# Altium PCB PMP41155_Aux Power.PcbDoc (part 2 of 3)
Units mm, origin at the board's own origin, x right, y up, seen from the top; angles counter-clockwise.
Board outline 40.5 x 70.5 mm, 6 copper layers (Top Layer, Signal Layer 1, Signal Layer 2, Signal Layer 3, Signal Layer 4, Bottom Layer), stack 1.573 mm thick; 130 components, 63 nets, 392 pads, 295 vias.
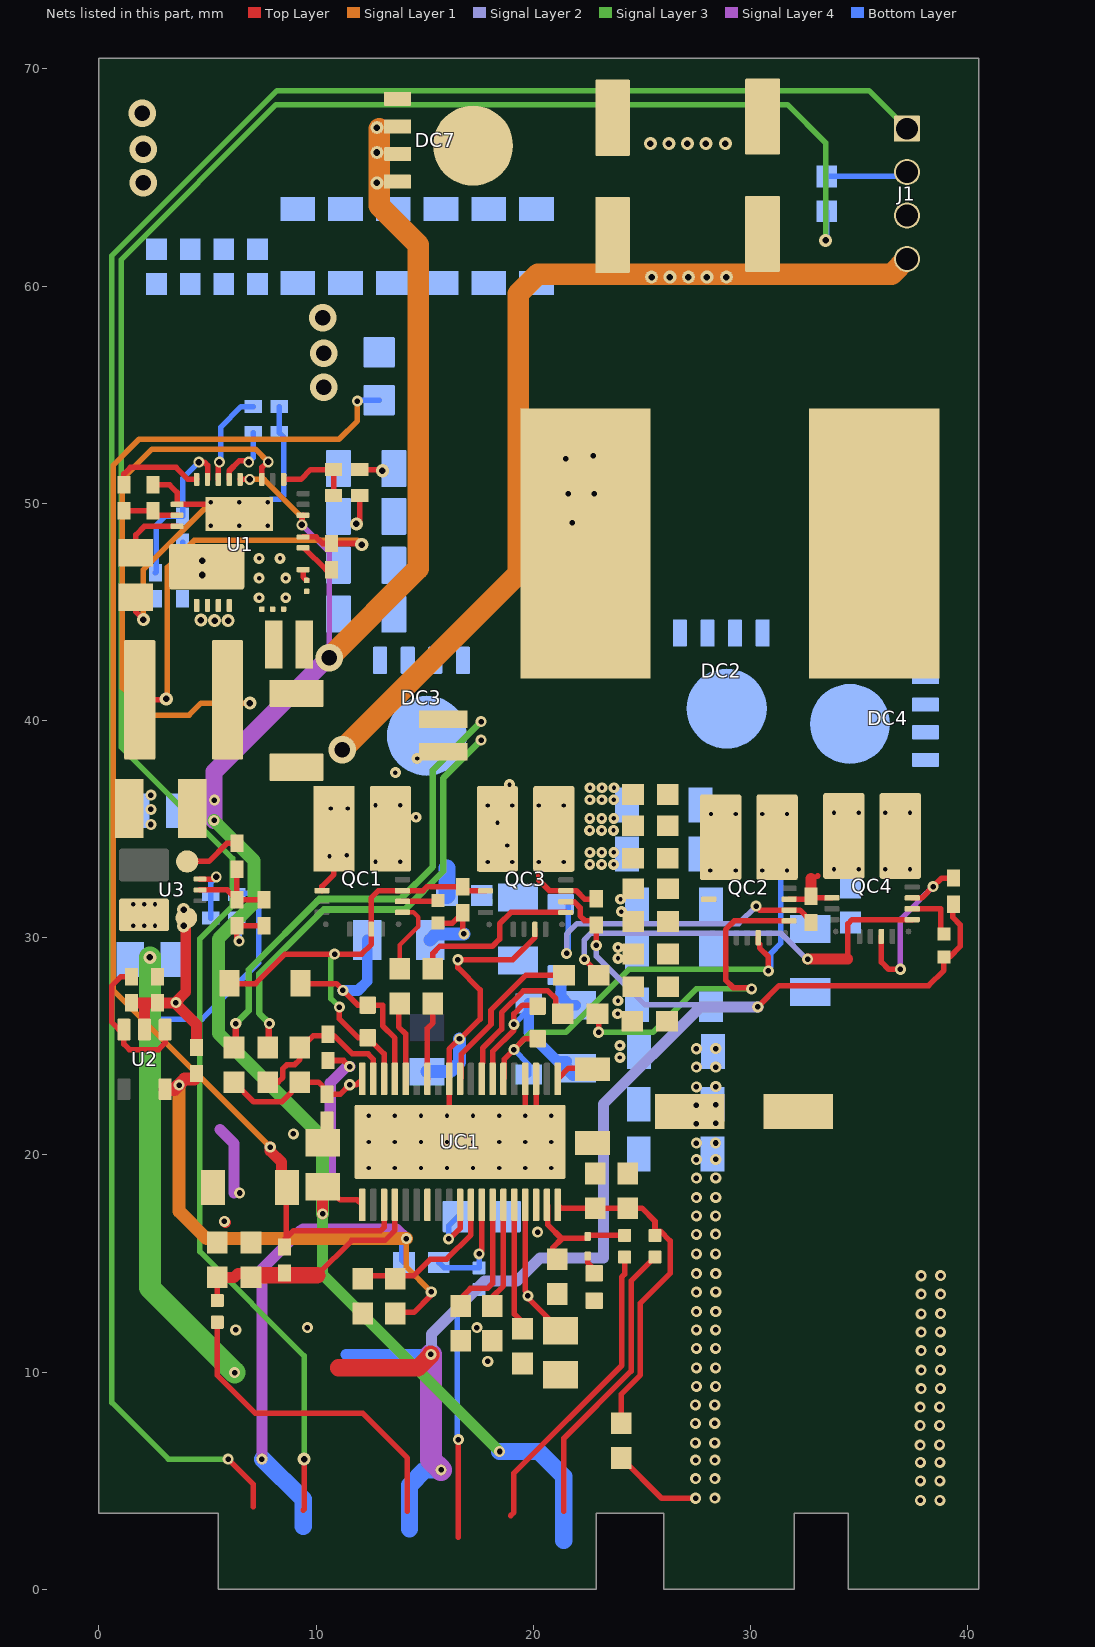
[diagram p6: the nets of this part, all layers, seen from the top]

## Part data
C1 C2: library part CMP-0007473-4, "CAP, CERM, 1800 pF, 100 V, +/- 10%, X7R, 0603", Cap_Case=0603, Manufacturer=MuRata, Supplier Part Number 1=490-1477-1-ND, TempCo=X7R, Tolerance_%=10%, Value1=Unknown, Value2=100V, ValueDisplayed=1800pF
C3 C12: library part CMP-0080610-1, "CAP, CERM, 0.1 µF, 25 V,+/- 10%, X7R, AEC-Q200 Grade 1, 0402", Cap_Case=0402, Manufacturer=TDK, Supplier Part Number 1=445-6902-1-ND, TempCo=X7R, Tolerance_%=10%, Value2=25V, ValueDisplayed=0.1µF
C4 C5 C6 C7: library part CMP-0125197-1, "100V 4.7uF X7R ±20% 1206 Multilayer Ceramic Capacitors MLCC - SMD/SMT ROHS", Manufacturer=HRE, Operating Temperature Range="-55°C to +125°C", TempCo=15%, Temperature Characteristic=X7R, Tolerance_%=20%, ValueDisplayed=4.7uF
C8: library part CMP-0080701-1, "CAP, CERM, 4.7 µF, 16 V,+/- 10%, X7R, AEC-Q200 Grade 1, 0805", Cap_Case=0805, Manufacturer=TDK, Supplier Part Number 1=445-8788-1-ND, TempCo=X7R, Tolerance_%=10%, Value2=16V, ValueDisplayed=4.7µF
C9: library part CMP-0091700-1, "47µF ±10% 16V Ceramic Capacitor X5R 1210 (3225 Metric)", Digikey Part Number=587-EMK325ABJ476KMHPCT-ND, Manufacturer="Taiyo Yuden", Mouser Part Number=963-EMK325ABJ476KMHP, Operating Temperature Range="-55°C to +85°C", TempCo=15%, Temperature Characteristic=X5R, Tolerance_%=10%, ValueDisplayed=47uF
C10: library part CMP-0006312-2, "CAP, CERM, 47 pF, 50 V, +/- 5%, C0G/NP0, AEC-Q200 Grade 0, 0402", Cap_Case=0402, Manufacturer=TDK, Supplier Part Number 1=445-12142-1-ND, TempCo=C0G/NP0, Tolerance_%=5%, Value1=Unknown, Value2=50V, ValueDisplayed=47pF
C11: library part CMP-0006323-2, "CAP, CERM, 6800 pF, 50 V, +/- 10%, X7R, AEC-Q200 Grade 1, 0402", Cap_Case=0402, Manufacturer=TDK, Supplier Part Number 1=445-6892-1-ND, TempCo=X7R, Tolerance_%=10%, Value1="0.391597 ohm", Value2=50V, ValueDisplayed=6800pF
C13 C14 C22: library part CMP-0006371-2, "CAP, CERM, 0.1 uF, 6.3 V, +/- 10%, B, 0402", Cap_Case=0402, Manufacturer=MuRata, Supplier Part Number 1=GRM155R70J104KA01D-ND, TempCo=B, Tolerance_%=10%, Value1=Unknown, Value2=6.3V, ValueDisplayed=0.1uF
C15 C16: library part CMP-0124190-1, "270 µF 16 V Aluminum - Polymer Capacitors Radial, Can - SMD 10mOhm 15000 Hrs @ 105°C", Digikey Part Number=565-APXJ160ARA271MF80JCT-ND, Leakage Current=864uA, Manufacturer=Chemi-Con, Mouser Part Number=661-XJ160ARA271MF80J, Operating Temperature Range="-55°C to +105°C", Tolerance_%=20%, ValueDisplayed=270uF
C19: library part CMP-0009211-2, "CAP, CERM, 47 uF, 16 V, +/- 10%, X5R, 1210", Cap_Case=1210, Manufacturer=MuRata, Supplier Part Number 1=GRM32ER61C476KE15L-ND, TempCo=X5R, Tolerance_%=10%, Value1=Unknown, Value2=16V, ValueDisplayed=47uF
C20: library part CMP-0007728-2, "CAP, CERM, 1 uF, 25 V, +/- 10%, X7R, 0805", Cap_Case=0805, Manufacturer=Kemet, Supplier Part Number 1=399-8004-1-ND, TempCo=X7R, Tolerance_%=10%, Value1=Unknown, Value2=25V, ValueDisplayed=1uF
C21: library part CMP-0007989-2, "CAP, CERM, 22 uF, 6.3 V, +/- 10%, X5R, 0805", Cap_Case=0805, Manufacturer="Samsung Electro-Mechanics", TempCo=X5R, Tolerance_%=10%, Value1=Unknown, Value2=6.3V, ValueDisplayed=22uF
C23: library part CMP-0078218-1, "CAP, CERM, 0.01 µF, 16 V,+/- 10%, X7R, 0402", Cap_Case=0402, Manufacturer=Kemet, Supplier Part Number 1=399-1038-1-ND, TempCo=X7R, Tolerance_%=10%, Value2=16V, ValueDisplayed=0.01µF
CC1 CC2 CC3 CC4 CC5 CC6 CC19 CC20 CC21 CC22 CC23 CC27 CC28 CC29 CC34 CC37: library part C3216X6S1H475K160AB, "CAP CER 4.7UF 100V X7S 1206", Cap_Case=1206, TempCo=X7S, Tolerance_%=10, Value2=100V, ValueDisplayed=4.7µF
CC7 CC8 CC9 CC10 CC11 CC12 CC13 CC14 CC15 CC16 CC17 CC18: "CAP, CERM, 0.022 µF, 100 V,+/- 10%, X7R, AEC-Q200 Grade 1, 0603", Cap_Case=0603, Manufacturer=TDK, Supplier Part Number 1=445-5814-1-ND, TempCo=X7R, Tolerance_%=10, Value1="0.083542 ohm", Value2=100V, ValueDisplayed=0.022µF
CC24 CC25 CC30 CC31: "CAP, CERM, 0.1 µF, 16 V,+/- 10%, X7R, AEC-Q200 Grade 1, 0402", Cap_Case=0402, Manufacturer=Kemet, Supplier Part Number 1=399-6828-1-ND, TempCo=X7R, Tolerance_%=10, Value2=16V, ValueDisplayed=0.1µF
CC26: library part EEE-FK1H220P, "CAP ALUM POLY HYB 22UF 63V SMD", Cap_Case=D, Manufacturer=Rubycon, Tolerance_%=20, Value1="0.88 ohm", Value2=63V, ValueDisplayed=22µF
CC32: library part CMP-0078699-1, "CAP, CERM, 47 µF, 10 V,+/- 20%, X5R, 0805", Cap_Case=0805, Manufacturer=MuRata, Supplier Part Number 1=490-9961-1-ND, TempCo=X5R, Tolerance_%=20%, Value2=10V, ValueDisplayed=47µF
CC33: "CAP, CERM, 220 pF, 50 V,+/- 10%, X7R, 0603", Cap_Case=0603, Manufacturer=MuRata, Supplier Part Number 1=490-1483-1-ND, TempCo=X7R, Tolerance_%=10, Value2=50V, ValueDisplayed=220pF
CC35: "CAP, CERM, 2.2 µF, 25 V,+/- 10%, X5R, 0805", Cap_Case=0805, Manufacturer=MuRata, Supplier Part Number 1=490-1701-1-ND, TempCo=X5R, Tolerance_%=10, Value1="0.006 ohm", Value2=25V, ValueDisplayed=2.2µF
CC36: "CAP, CERM, 68 pF, 50 V,+/- 5%, C0G/NP0, 0603", Cap_Case=0603, Manufacturer=AVX, Supplier Part Number 1=478-1173-1-ND, TempCo=C0G/NP0, Tolerance_%=5, Value1="0.144 ohm", Value2=50V, ValueDisplayed=68pF
CC38: "CAP, CERM, 1000 pF, 50 V,+/- 5%, C0G/NP0, 0603", Cap_Case=0603, Manufacturer=MuRata, Supplier Part Number 1=490-1451-1-ND, TempCo=C0G/NP0, Tolerance_%=5, Value2=50V, ValueDisplayed=1000pF
CC39 CC40: "CAP, CERM, 47 pF, 50 V,+/- 1%, C0G/NP0, 0402", Cap_Case=0402, Manufacturer=MuRata, Supplier Part Number 1=490-6241-1-ND, TempCo=C0G/NP0, Tolerance_%=1, Value2=50V, ValueDisplayed=47pF
CC41: "CAP, CERM, 2200 pF, 50 V,+/- 10%, X5R, 0603", Cap_Case=0603, Manufacturer=MuRata, Supplier Part Number 1=GRM188R61H222KA01D-ND, TempCo=X5R, Tolerance_%=10, Value2=50V, ValueDisplayed=2200pF
CC42 CC43: library part CMP-0120699-1, "0.1 µF ±5% 16V Ceramic Capacitor X7R 0603 (1608 Metric)", Digikey Part Number=478-KGM15AR71C104JTCT-ND, Manufacturer="KYOCERA AVX", Mouser Part Number=581-0603YC104J, Operating Temperature Range="-55°C to +125°C", TempCo=15%, Temperature Characteristic=X7R, Tolerance_%=5%, ValueDisplayed=100nF
CC44: library part CMP-0095696-1, "Cap Ceramic 22nF 50V X7R ±10% Pad SMD 0603 +125°C T/R", Manufacturer=Samsung, Operating Temperature Range="-55°C to +125°C", TempCo=0.15, Temperature Characteristic=X7R, Tolerance_%=10%, ValueDisplayed=22nF
CC45: library part CMP-0007168-4, "CAP, CERM, 820 pF, 25 V, +/- 5%, C0G/NP0, 0603", Cap_Case=0603, Manufacturer=MuRata, Supplier Part Number 1=81-GRM185C1E821JA01D, TempCo=C0G/NP0, Tolerance_%=5%, Value1=Unknown, Value2=25V, ValueDisplayed=820pF
CC46: library part CMP-0007572-2, "CAP, CERM, 0.22 uF, 25 V, +/- 20%, X7R, 0805", Cap_Case=0805, Manufacturer=AVX, Supplier Part Number 1=478-3757-1-ND, TempCo=X7R, Tolerance_%=20%, Value1="0.016 ohm", Value2=25V, ValueDisplayed=0.22uF
DC1: library part CMP-0090564-1, "Diode Schottky 40V 500mA Surface Mount SOD-123", Digikey Part Number=NRVB0540T1GOSCT-ND, Forward Current=0.5A, Manufacturer="On Semiconductor", Max Surge Forward Current=5.5A, Mouser Part Number=863-NRVB0540T1G, Operating Temperature Range="-55°C to +150°C", Peak Reverse Current=20uA
DC2 DC3 DC4 DC7: library part CMP-0032275-1, "Diode 100 V 30A Surface Mount PowerFlat™ (5x6)", Digikey Part Number=497-10342-1-ND, Forward Current=30A, Manufacturer=STMicroelectronics, Max Surge Forward Current=200A, Mouser Part Number=511-STPS30M100DJF-TR, Operating Temperature Range="to +150°C", Peak Reverse Current=100uA
DC5 DC6: library part CMP-0077600-3, "Diode, Zener, 5.6 V, 500 mW, SOD-123", Manufacturer=Vishay-Semiconductor, Power_W=500mW, Value1=0.5W
J1: library part CMP-0125223-1, "Conn Socket Strip SKT 4 POS 2mm Solder ST Thru-Hole Box", Current_A=3A, Digikey Part Number=831-87-004-10-001101-ND, Manufacturer=Preci-Dip, Mouser Part Number=437-8318700410001101, Operating Temperature Range="-55°C to +125°C", Voltage_V=150V
L1: library part CMP-0093175-1, "Shielded Power Inductors 3.3uH 20% tol, 6.5mOhm 16.6A", Manufacturer=Coilcraft, Operating Temperature Range=to, Self Resonant Frequency=24MHz, Test Frequency=1MHz, Tolerance_%=20%
LC1: library part CMP-0064042-1, ValueDisplayed=2.2uH
LOGO1: library part CMP-0074837-1, "IEC 61010-1 Hot Surface Warning"
Logo2: library part Pb-Free
Logo3: library part CMP-0074769-1
Logo4: library part CMP-0074847-1, "FCC_disclaimer"
QC1 QC2 QC3 QC4: library part CMP-0037654-1, "100-V, 64-A GaN with Integrated Driver", Manufacturer="Texas Instruments", Max Supply Voltage=5.25V, Min Supply Voltage=4.75V, Nominal Supply Current=3mA, Operating Temperature Range="-40°C to +125°C"
R1 R2: library part CMP-02407-004899-1, "RES Thick Film, 3.01Ω, 1%, 0.063W, 200ppm/°C, 0402", Case Code (Imperial)=0402, Case Code (Metric)=1005, Max Operating Temperature=155°C, Max Power Dissipation=63mW, Min Operating Temperature=-55°C, Package Quantity=10000, Resistance=3.01R, Temperature Coefficient=200ppm/°C, Tolerance=1%, Voltage Rating=50V
R3 R4: library part CMP-0016888-3, "RES, 2.55, 1%, 0.25 W, AEC-Q200 Grade 0, 1206", Manufacturer=Vishay-Dale, Power_W=250mW, Supplier Part Number 1=541-2.55FFCT-ND, TempCo="100 ppm/C", Tolerance_%=1%, Value2=0.25W, Value_Code=2R55, ValueDisplayed=2.55
R5: library part CMP-0022550-4, "RES, 681 k, 1%, 0.1 W, AEC-Q200 Grade 0, 0603", Manufacturer=Vishay-Dale, Power_W=100mW, Supplier Part Number 1=541-681KHCT-ND, TempCo="100 ppm/C", Tolerance_%=1%, Value2=0.1W, Value_Code=681k
R6 R8 R9 R10: library part CMP-0031873-1, "0 Ohms Jumper Chip Resistor 0402 (1005 Metric) Anti-Sulfur, Current Sense, Flame Retardant Coating, Moisture Resistant, Safety Metal Foil", Digikey Part Number=4463-D1LPC0402CJUMPF-T10CT-ND, Manufacturer="Thin Film Technology", Max Current=20A, Operating Temperature Range="-55°C to +170°C"
R7: library part CMP-0022042-4, "RES, 13.0 k, 1%, 0.1 W, AEC-Q200 Grade 0, 0603", Manufacturer=Vishay-Dale, Power_W=100mW, Supplier Part Number 1=541-13.0KHCT-ND, TempCo="100 ppm/C", Tolerance_%=1%, Value2=0.1W, Value_Code=13k0, ValueDisplayed=13.0k
R11: library part CMP-0026753-1, "RES, 100 k, 1%, 0.063 W, AEC-Q200 Grade 0, 0402", Manufacturer="Stackpole Electronics Inc", Power_W=63mW, Supplier Part Number 1=RMCF0402FT100KCT-ND, TempCo="100 ppm/C", Tolerance_%=1%, Value2=0.063W, Value_Code=100k
R12: library part CMP-0015100-2, "RES, 0.005, 1%, 1 W, AEC-Q200 Grade 0, 0508", Manufacturer="Susumu Co Ltd", Power_W=1W, Supplier Part Number 1=754-KRL2012MR005FT1, TempCo="25 ppm/C", Tolerance_%=1%, Value_Code=5L000, ValueDisplayed=0.005
R13: library part CMP-0026468-2, "RES, 5.76 k, 1%, 0.063 W, AEC-Q200 Grade 0, 0402", Manufacturer=Vishay-Dale, Power_W=63mW, Supplier Part Number 1=541-5.76KLCT-ND, TempCo="100 ppm/C", Tolerance_%=1%, Value2=0.063W, Value_Code=5k76, ValueDisplayed=5.76k
R14: library part CMP-0026718-1, "RES, 49.9 k, 1%, 0.063 W, 0402", Manufacturer=Rohm, Power_W=63mW, Supplier Part Number 1=RHM49.9KLCT-ND, TempCo="100 ppm/C", Tolerance_%=1%, Value2=0.063W, Value_Code=49k9, ValueDisplayed=49.9k
R15: library part CMP-0026535-2, "RES, 71.5 k, 1%, 0.063 W, AEC-Q200 Grade 0, 0402", Manufacturer=Vishay-Dale, Power_W=63mW, Supplier Part Number 1=541-71.5KLCT-ND, TempCo="100 ppm/C", Tolerance_%=1%, Value2=0.063W, Value_Code=71k5, ValueDisplayed=71.5k
R16: library part CMP-0026163-2, "RES, 20.5 k, 1%, 0.063 W, AEC-Q200 Grade 0, 0402", Manufacturer=Vishay-Dale, Power_W=63mW, Supplier Part Number 1=541-20.5KLCT-ND, TempCo="100 ppm/C", Tolerance_%=1%, Value2=0.063W, Value_Code=20k5, ValueDisplayed=20.5k
R17 R19: library part CMP-0026403-2, "RES, 49.9 k, 1%, 0.063 W, AEC-Q200 Grade 0, 0402", Manufacturer=Vishay-Dale, Power_W=63mW, Supplier Part Number 1=541-49.9KLCT-ND, TempCo="100 ppm/C", Tolerance_%=1%, Value2=0.063W, Value_Code=49k9, ValueDisplayed=49.9k
R18: library part CMP-0025885-5, "RES, 0, 5%, 0.1 W, 0603", Manufacturer=Yageo, Power_W=100mW, Supplier Part Number 1=311-0.0GRCT-ND, TempCo="200 ppm/C", Tolerance_%=5%, Value2=0.1W, Value_Code=0000, ValueDisplayed=0
R20: library part CMP-0026728-1, "RES, 220 k, 1%, 0.0625 W, 0402", Manufacturer="Yageo America", Power_W=62.5mW, Supplier Part Number 1=311-220KLRCT-ND, TempCo="100 ppm/C", Tolerance_%=1%, Value2=0.0625W, Value_Code=220k
R21 R22: library part CMP-0078244-2, "RES, 30.0 k, 1%, 0.063 W, AEC-Q200 Grade 0, 0402", Manufacturer=Vishay-Dale, Power_W=63mW, Supplier Part Number 1=541-30.0KLCT-ND, TempCo="100 ppm/C", Tolerance_%=1%, Value2=0.063W, Value_Code=30k0, ValueDisplayed=30.0k
RC1 RC2: library part CMP-0018270-2, "RES, 3.30, 1%, 0.25 W, 1206", Manufacturer="Yageo America", Power_W=250mW, Supplier Part Number 1=311-3.30FRCT-ND, TempCo="200 ppm/C", Tolerance_%=1%, Value2=0.25W, Value_Code=3R30, ValueDisplayed=3.30
RC3: library part CMP-0015357-3, "RES, 0.002, 2%, 1 W, 0508", Manufacturer="Susumu Co Ltd", Power_W=1W, Supplier Part Number 1=408-1592-1-ND, TempCo="100 ppm/C", Tolerance_%=2%, Value_Code=2L000, ValueDisplayed=0.002
RC4 RC14: library part CMP-0096818-1, "0 Ohms Jumper 0.245W Chip Resistor 0805 (2012 Metric) - Metal Element", Digikey Part Number=JR0805X35ECT-ND, Manufacturer=Ohmite, Mouser Part Number=588-JR0805X35E, Operating Temperature Range="-55°C to +150°C", Power_W=245mW
RC5: library part CMP-0026535-2, "RES, 71.5 k, 1%, 0.063 W, AEC-Q200 Grade 0, 0402", Manufacturer=Vishay-Dale, Power_W=63mW, Supplier Part Number 1=541-71.5KLCT-ND, TempCo="100 ppm/C", Tolerance_%=1%, Value2=0.063W, Value_Code=71k5, ValueDisplayed=DNP
RC6 RC8: "RES, 100, 1%, 0.1 W, 0603", Manufacturer="Yageo America", Power_W=0.1, Supplier Part Number 1=311-100HRCT-ND, TempCo="200 ppm/C", Tolerance_%=1, Value1=1%, Value2=0.1W, Value_Code=100R, ValueDisplayed=100
RC7: "RES, 10.0 k, 1%, 0.1 W, 0603", Manufacturer=Vishay-Dale, Power_W=0.1, Supplier Part Number 1=541-10.0KHCT-ND, TempCo="100 ppm/C", Tolerance_%=1, Value1=1%, Value2=0.1W, Value_Code=10k0, ValueDisplayed=10.0k
RC9: "RES, 100, 1%, 0.1 W, 0603", Manufacturer=Vishay-Dale, Power_W=0.1, Supplier Part Number 1=541-100HCT-ND, TempCo="100 ppm/C", Tolerance_%=1, Value1=1%, Value2=0.1W, Value_Code=100R, ValueDisplayed=100
RC10: "RES, 10.7 k, 1%, 0.1 W, 0603", Manufacturer=Vishay-Dale, Power_W=0.1, Supplier Part Number 1=541-10.7KHCT-ND, TempCo="100 ppm/C", Tolerance_%=1, Value1=1%, Value2=0.1W, Value_Code=10k7, ValueDisplayed=10.7k
RC11 RC12 RC13 RC15: library part CMP-0025697-4, "RES, 0, 5%, 0.1 W, AEC-Q200 Grade 0, 0603", Manufacturer=Vishay-Dale, Power_W=100mW, Supplier Part Number 1=541-0.0GCT-ND, TempCo="200 ppm/C", Tolerance_%=5%, Value2=0.1W, Value_Code=0000, ValueDisplayed=0
RC16: library part CMP-0089989-1, "2.87 kOhms ±1% 0.1W, 1/10W Chip Resistor 0402 (1005 Metric) Automotive AEC-Q200, Moisture Resistant Thick Film", Digikey Part Number=2019-RK73H1ETTP2871FCT-ND, Manufacturer="KOA Speer", Mouser Part Number=660-RK73H1ETTP2871F, Operating Temperature Range="-55°C to +155°C", Power_W=100mW, TempCo=100ppm/°C, Tolerance_%=1%
RC17: "RES, 8.25 k, 1%, 0.1 W, 0603", Manufacturer=Vishay-Dale, Power_W=0.1, Supplier Part Number 1=541-8.25KHCT-ND, TempCo="100 ppm/C", Tolerance_%=1, Value1=1%, Value2=0.1W, Value_Code=8k25, ValueDisplayed=8.25k
RC18 RC19: "RES, 100 k, 1%, 0.1 W, 0603", Manufacturer=Vishay-Dale, Power_W=0.1, Supplier Part Number 1=541-100KHCT-ND, TempCo="100 ppm/C", Tolerance_%=1, Value1=1%, Value2=0.1W, Value_Code=100k
U1: library part CMP-0096026-3, "80-V, 8-A Synchronous DC/DC Buck Converter With Ultra-Low IQ, VQFN29", Manufacturer="Texas Instruments", Max Supply Voltage=80V, Min Supply Voltage=4.5V, Operating Temperature Range="-40°C to +150°C", Output Voltage=0.8-55V, Switching Frequency=0.2-2.2MHz
U2: library part CMP-0073750-1, "Capacitor-Free, 150-mA, LDO Regulator w/ Foldback Current Limit, DBV0005A (SOT-23-5)", Alternate Manufacturer="Texas Instruments"
U3: library part CMP-0097277-2, "3-V to 17-V Input, 3-A Synchronous Buck Module, QFN-FCMOD7", Manufacturer="Texas Instruments", Max Supply Voltage=17V, Min Supply Voltage=3V, Nominal Supply Current=100-400uA, Operating Temperature Range="-40°C to +125°C", Output Voltage=0.6-10V, Switching Frequency=1200/2000kHz
UC1: library part CMP-0094661-2, "Wide VIN Bidirectional 4 Switch Buck-Boost Controller", Manufacturer="Texas Instruments", Max Supply Voltage=78V, Min Supply Voltage=2.8V, Nominal Supply Current=25uA, Operating Temperature Range="-40°C to +125°C", Output Voltage=3.3-78V, Switching Frequency=100-2000kHz

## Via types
v1: diameter 0.508, hole 0.254, Top Layer to Bottom Layer, 138 vias
v2: diameter 0.5, hole 0.2, Top Layer to Bottom Layer, tented both sides, 64 vias
v3: diameter 0.5, hole 0.2, Top Layer to Bottom Layer, 48 vias
v4: diameter 0.6, hole 0.3, Top Layer to Bottom Layer, 29 vias
v5: diameter 1.27, hole 0.711, Top Layer to Bottom Layer, 8 vias
v6: diameter 0.5, hole 0.3, Top Layer to Bottom Layer, 7 vias
v7: diameter 0.508, hole 0.254, Top Layer to Bottom Layer, tented both sides, 1 vias

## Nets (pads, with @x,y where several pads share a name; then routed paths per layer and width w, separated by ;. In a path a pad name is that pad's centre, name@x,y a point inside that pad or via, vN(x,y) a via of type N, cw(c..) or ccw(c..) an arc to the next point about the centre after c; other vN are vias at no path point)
3V3: C13.1 RC7.1 RC9.1 U2.5 | length 45.1
  Top Layer w0.254: RC9.1@13.5,12.75 14.5,12.75 15.3,13.55 v1@15.3,13.75
  Top Layer w0.6: U2.5@3.05,23.025 3.475,23.025 3.95,23.5 C13.1@4.4,23.5
  Signal Layer 4 w0.508: v1(7.5,6) 7.5,14.75 9.271,16.521 9.302,16.521 9.385,16.603 13.697,16.603 v1(14.15,16.15)
  Signal Layer 1 w0.254: v1(14.15,16.15) 14.15,14.85 v1(15.3,13.7)
  Signal Layer 1 w0.6: v1(3.695,23.214) 3.695,17.405 4.95,16.15 v1(14.15,16.15)
  Bottom Layer w0.254: v1(7.5,6) v1@7.55,6 ; RC7.1@14.05,15.05 13.95,15.15 13.95,15.85 v1@14.2,16.1
  Bottom Layer w0.8: v1@7.55,6 9.4,4.15 9.4,2.9
5V: C14.1 C21.1 C22.1 CC30.1 CC31.1 QC3.3 R2.2 R20.2 U2.1 U2.3 U3.3 | length 106.4
  Top Layer w0.254: C22.1@1.5,28.2 1,28.2 0.6,27.8 0.6,26.1 0.925,25.775 U2.3@1.15,25.775 1.15,25.1 1.4,24.85 2.75,24.85 3.05,25.15 U2.1@3.05,25.775 ; QC3.3@21.495,31.663 21.716,31.663 21.718,31.661 21.873,31.661 21.942,31.593 22.154,31.381 22.154,31.004 22.367,30.791 22.722,30.791 22.895,30.618 CC30.1@22.895,30.588 v1(22.895,29.653) ; v1(30.33,26.814) 31.315,27.8 38.2,27.8 38.9,28.5 R2.2@38.9,29.125 39.175,29.125 39.65,29.6 39.65,30.6 39.3,30.95 39.3,31.5 CC31.1@39.35,31.55
  Top Layer w0.8: 11.031,10.2 14.7,10.2 15.284,10.784 v1(15.284,10.819)
  Signal Layer 4 w1: v1(15.284,10.819) 15.284,5.966 v1(15.75,5.5)
  Signal Layer 3 w1: v4(2.35,29.1) 2.35,13.885 v1(6.25,9.985)
  Signal Layer 2 w0.254: v1(22.895,29.653) 22.895,29.155 25.136,26.914 27.914,26.914
  Signal Layer 2 w0.508: v1@15.306,10.819 15.306,11.756 17.753,14.203 19.253,14.203 20.3,15.25 23.229,15.25 23.229,22.358 27.686,26.814 v1(30.33,26.814)
  Bottom Layer w0.254: 2.4,28.6 2.4,26.6 2.75,26.25 4.75,26.25 7.35,28.85 7.35,31.85 7.15,32.05 6.4,32.05 R20.2@6.35,32
  Bottom Layer w0.508: 11.369,10.819 v1(15.284,10.819)
  Bottom Layer w0.8: 14.3,2.8 14.3,4.8 15,5.5 v1(15.75,5.5)
  other v3: 1.585,30.55 2.085,30.55 2.585,30.55 1.585,31.55 2.085,31.55 2.585,31.55
12V: C9.2 C19.1 C20.1 CC35.2 DC7.1 DC7.2 DC7.3 DC7.4 R12.2 R19.2 U1.6 U1.12 U3.1 UC1.1 | length 96.4
  Top Layer w0.254: U3.1@4.062,33.512 5.062,33.512 5.9,34.35 R19.2@6.35,34.35 ; U1.12@6.5,51.1 v6(6.941,51.1) ; v6(9.345,49.006) 9.345,49.395 U1.6@9.4,49.45 ; CC35.2@10.434,18.158 10.878,18.158 11.1,17.936 11.889,17.936 UC1.1@12.125,17.7
  Top Layer w0.508: v1(10.3,17.289) 10.3,18.267 CC35.2@10.434,18.4
  Signal Layer 4 w0.254: v6(9.345,49.006) 10.6,47.751 v5(10.6,42.9)
  Signal Layer 4 w0.8: v1(5.3,35.4) 5.3,37.65 v5@10.55,42.9
  Signal Layer 3 w0.508: v1(10.3,17.289) 10.3,14.5 v1(18.45,6.35)
  Signal Layer 3 w0.6: v1(5.3,35.4) 7.15,33.55 7.15,31.6 5.5,29.95 5.5,25.6 10.3,20.8 v1(10.3,17.289)
  Signal Layer 1 w0.254: v6(6.941,51.1) 7.6,51.1 9.35,49.35 v6@9.35,49.05
  Signal Layer 1 w1: v5(10.6,42.9) 14.7,47 14.7,61.9 12.9,63.7 ; v4@12.9,64.75 12.9,63.7 ; v4@12.9,67.25 12.9,66.15 12.9,63.7
  Bottom Layer w0.8: v1(18.45,6.35) 20.25,6.35 21.4,5.2 21.4,2.25
  other v1: 5.311,36.338
  other v4: 12.8,64.75 12.8,66.15 12.8,67.3
12VFAN: C15.2 C16.2 DC7.5 J1.3
  other v4: 25.389,66.563 26.239,66.563 27.089,66.563 27.939,66.563 28.839,66.563
CSA_DISCH: C2.1 CC24.2 CC42.2 DC3.5 DC5.2 QC1.4 QC1.6 QC1.14 QC3.7 QC3.8 RC3.1 RC6.2 UC1.36 | length 43.8
  Top Layer w0.254: DC5.2@6.362,27.887 7.214,27.887 8.573,29.246 v1(10.846,29.246) 12.096,29.246 12.545,29.695 QC1.14@12.545,30.397 12.545,31.851 12.866,32.172 14.922,32.172 15.1,32.35 CC24.2@16.75,32.35 16.937,32.163 QC3.8@17.795,32.163 ; v1(11.071,26.806) 11.071,26.262 11.933,25.4 CC42.2@12.375,25.4 13.125,24.65 UC1.36@13.125,23.5
  Top Layer w0.305: RC6.2@7.82,25 7.82,26.02 v1(7.85,26.05)
  Signal Layer 3 w0.254: v1(10.846,29.246) 10.677,29.077 10.677,27.2 v1(11.071,26.806)
  Signal Layer 3 w0.305: v1(7.85,26.05) 7.383,26.517 7.383,28.331 10.351,31.3 14.087,31.3 15.848,33.061 15.848,37.348 v1@17.65,39.15
  Bottom Layer w0.254: 16.023,33.208 16.04,33.225
  Bottom Layer w0.8: C2.1@16.023,31.945 16.023,33.208
  other v1: 17.6,39.1
  other v2: 17.895,33.488 19.035,33.488 12.73,33.497 13.87,33.497 18.8,34.25 18.35,35.3 14.6,35.55 12.73,36.097 13.87,36.097 17.895,36.088 19.035,36.088 18.9,37.05 13.65,37.6 14.65,38.25
CSB_DISCH: LC1.1 RC3.2 RC8.2 | length 21.9
  Top Layer w0.305: RC8.2@6.22,24.95 6.3,25.03 v1(6.3,26.05)
  Signal Layer 3 w0.305: v1(6.3,26.05) 6.9,26.65 6.9,28.531 10.151,31.783 13.887,31.783 15.365,33.261 15.365,37.715 v1(17.6,39.95)
  other v1: 21.8,49.1 21.6,50.45 22.8,50.45 21.5,52.05 22.75,52.2
DISCH_COMP: CC45.1 R8.2 RC16.2 UC1.18 | length 5.7
  Top Layer w0.254: UC1.18@20.625,17.7 20.67,17.655 20.67,16.78 21.307,16.143 ; CC45.1@20.9,15.373 20.9,15.736 21.307,16.143 ; RC16.2@22.5,16.173 21.337,16.173 21.307,16.143 ; RC16.2@22.5,16.25 22.55,16.3 R8.2@24.2,16.3
DISCH_EN: CC38.1 R10.2 RC5.1 RC10.2 UC1.4 | length 11.5
  Top Layer w0.254: R10.2@5.45,13.3 RC10.2@5.45,14.367 ; 10.05,14.467 11.65,16.067 13.167,16.067 13.625,16.525 UC1.4@13.625,17.7
  Top Layer w0.508: RC10.2@5.45,14.367 6.217,14.367 6.4,14.55 6.817,14.55 CC38.1@7,14.367
  Top Layer w0.75: CC38.1@6.95,14.467 10.05,14.467
DISCH_SS: CC46.1 UC1.16 | length 6.4
  Top Layer w0.254: UC1.16@19.625,17.7 19.625,13.742 v1@19.75,13.617 ; v1(19.75,13.517) 19.75,13.416 CC46.1@21.25,11.916
  Signal Layer 3 w0.254: v1@19.695,13.562 v1@19.75,13.617
GHA: QC1.2 RC11.2 | length 3.6
  Top Layer w0.2: RC11.2@13.85,28.571 13.85,29.663 14.7,30.513 14.7,30.95 14.478,31.172 QC1.2@13.97,31.172
GHB: QC2.2 RC13.2 | length 15.5
  Top Layer w0.254: RC13.2@22.95,26.5 23,26.45 v1(23,25.65) ; v1(30.05,27.65) 30.001,27.699 29.201,27.699 28.85,28.05 28.85,30.377 29.248,30.775 QC2.2@31.775,30.775
  Signal Layer 3 w0.254: v1(23,25.65) 25.5,25.65 27.5,27.65 v1(30.05,27.65)
GLA: QC3.2 RC12.2 | length 8
  Top Layer w0.254: RC12.2@15.367,28.571 15.367,29.283 15.685,29.6 18.108,29.6 18.45,29.942 18.45,30.645 18.968,31.163 QC3.2@21.495,31.163
GLB: QC4.2 RC15.2 | length 19.3
  Top Layer w0.254: v1(22.35,29) 23.009,28.341 RC15.2@23.009,28.281 ; v1(32.625,29.019) v1@32.628,29.022 ; 34.475,29.022 34.475,30.636 34.676,30.837 QC4.2@37.443,30.837
  Top Layer w0.5: v1@32.628,29.022 34.475,29.022
  Signal Layer 2 w0.254: v1(22.35,29) 22.336,29.014 22.336,29.884 22.663,30.212 31.388,30.212 v1@32.628,28.972
HB1: CC42.1 DC5.1 RC1.1 UC1.35 | length 10.7
  Top Layer w0.254: DC5.1@9.638,27.887 10.928,27.887 v1(11.236,27.579) 11.915,26.9 CC42.1@12.375,26.9 13.056,26.9 13.056,25.949 13.625,25.38 UC1.35@13.625,23.5
  Bottom Layer w0.5: v1(11.236,27.579) 11.929,27.579 12.35,28 RC1.1@12.35,29.9
HB2: CC43.1 DC6.1 RC2.2 UC1.26 | length 10.3
  Top Layer w0.254: UC1.26@18.125,23.5 18.125,24.768 19.1,25.743 v1(19.1,26.016) 19.1,26.5 19.5,26.9 20.15,26.9 CC43.1@20.2,26.85
  Bottom Layer w0.254: v1(19.1,26.016) DC6.1@19.787,26.703
  Bottom Layer w0.5: DC6.1@19.787,26.979 19.787,26.703 19.787,25.645 21.116,24.316 RC2.2@21.532,24.316 ; RC2.2@21.48,24.008 21.825,23.664 21.825,23.767 RC2.2@21.532,24.06
NetC1_2: C1.2 R3.2
NetC2_2: C2.2 R4.2
NetC3_1: C3.1 L1.1 U1. U1.5 U1.20 U1.21 U1.22 | length 19.6
  Top Layer w0.254: L1.1@1.88,40.95 3.05,40.95 v4(3.1,41) ; U1.5@9.4,48.45 10,48.45 10.3,48.15 12.05,48.15 v4(12.1,48.1)
  Signal Layer 1 w0.254: v4@3.15,41.084 3.15,47.05 4.4,48.3 11.9,48.3 v4(12.1,48.1)
  other v4: 4.75,46.7 4.75,47.35
NetC3_2: C3.2 U1.4 | length 1.7
  Top Layer w0.254: U1.4@9.4,47.95 9.45,47.95 10.45,46.95 C3.2@10.7,46.95
NetC8_2: C8.2 U1.19 | length 2.9
  Top Layer w0.254: C8.2@1.7,47.716 1.7,48.55 2.095,48.945 3.595,48.945 U1.19@3.6,48.95
NetC10_1: C10.1 R13.2 U1.15 | length 7.5
  Top Layer w0.254: v6(4.6,51.9) 4.85,51.9 5,51.75 U1.15@5,51.1
  Bottom Layer w0.254: C10.1@2.6,46.8 2.65,46.85 2.65,49 3.05,49.4 R13.2@3.85,49.4 3.85,51.15 v6(4.6,51.9)
NetC11_1: C11.1 R13.1 | length 1.4
  Bottom Layer w0.254: C11.1@3.85,46.8 R13.1@3.85,48.2
NetC12_1: C12.1 R14.1 U1.18 | length 2.5
  Top Layer w0.254: R14.1@1.15,49.65 C12.1@2.5,49.65 2.7,49.45 U1.18@3.6,49.45
NetC23_1: C23.1 R19.1 R22.2 U3.6 | length 4.5
  Top Layer w0.254: U3.6@4.65,32.2 5.9,32.2 R22.2@6.35,31.75 ; R19.1@6.35,33.15 R22.2@6.35,31.75 ; C23.1@7.6,31.75 R22.2@6.35,31.75
NetCC24_1: CC24.1 R1.1 RC1.2 | length 4
  Top Layer w0.254: R1.1@15.6,30.675 16.275,30.675 CC24.1@16.75,31.15 16.75,30.229 v1(16.8,30.179)
  Bottom Layer w0.6: RC1.2@15.25,29.9 15.529,30.179 v1(16.8,30.179)
NetCC25_1: CC25.1 DC1.1 QC2.3 | length 15.2
  Top Layer w0.254: v1(30.253,31.453) 30.432,31.275 QC2.3@31.775,31.275 32.274,31.275 32.768,30.781 32.776,30.781 CC25.1@32.776,30.704
  Signal Layer 2 w0.254: v1(21.532,29.279) 21.532,30.169 22.013,30.65 29.45,30.65 v1@30.272,31.472
  Bottom Layer w0.254: v1(21.532,29.279) 21.6,29.347 DC1.1@21.6,31.444
NetCC36_1: CC36.1 CC39.1 RC6.1 UC1.37 | length 7.6
  Top Layer w0.254: RC6.1@7.77,23.35 8.25,23.35 8.47,23.57 8.47,23.976 8.649,24.155 9.005,24.155 9.25,24.4 CC36.1@9.25,24.95 ; CC36.1@9.325,24.95 9.875,25.5 10.55,25.5 10.816,25.5 11.666,24.65 12.393,24.65 12.625,24.418 UC1.37@12.625,23.5
NetCC36_2: CC36.2 CC40.1 RC8.1 UC1.38 | length 7.2
  Top Layer w0.254: RC8.1@6.22,23.35 7.12,22.45 8.425,22.45 9.325,23.35 10.1,23.35 CC40.1@10.575,22.875 ; CC40.1@10.5,22.8 10.675,22.8 11.115,22.8 v1(11.548,23.233) 11.858,23.233 UC1.38@12.125,23.5
NetCC37_1: CC37.1 RC4.2 RC5.2 UC1.3 | length 59.5
  Top Layer w0.254: RC5.2@8.55,15.767 8.55,16.1 8.971,16.521 12.978,16.521 13.125,16.667 UC1.3@13.125,17.7 ; RC5.2@8.617,15.933 8.617,18.467 CC37.1@8.65,18.5
  Top Layer w0.508: v1(7.887,20.36) 7.887,20.193 8.4,19.68 CC37.1@8.4,18.25
  Signal Layer 1 w0.254: v1(7.887,20.36) 0.65,27.596 0.65,51.75 1.85,52.95 11.05,52.95 11.9,53.8 v1(11.9,54.7)
  Bottom Layer w0.254: v1(11.9,54.7) 11.95,54.75 RC4.2@12.9,54.75
NetCC41_2: CC41.2 RC9.2 UC1.11 | length 7.4
  Top Layer w0.254: CC41.2@11.9,14.45 13.65,14.45 14.5,14.45 15.255,15.205 16.005,15.205 17.125,16.325 UC1.11@17.125,17.7
NetCC44_2: CC44.2 RC16.1 | length 0.9
  Top Layer w0.254: RC16.1@22.5,15.35 22.5,15.05 22.8,14.75 CC44.2@22.8,14.55
NetDC1_2: DC1.2 RC2.1 | length 1.5
  Bottom Layer w0.5: DC1.2@21.267,27.967 21.267,27.587 21.275,27.579 21.275,27.294 21.675,26.894 RC2.1@21.95,26.894
NetJ1_2: J1.2 R18.2 | length 3.8
  Bottom Layer w0.254: R18.2@33.5,65.05 37,65.05 J1.2@37.2,65.25
NetL1_2: L1.2 R12.1 U1.11 | length 24.7
  Top Layer w0.254: U1.11@7.5,51.1 7.5,51.65 v6@7.8,51.95
  Signal Layer 1 w0.254: v4(6.95,40.8) 4.7,40.8 4.15,40.25 2.35,40.25 1.082,41.518 1.082,51.132 2.45,52.5 7.201,52.5 v6(7.795,51.906)
NetQC1_3: QC1.3 R1.2 | length 1.7
  Top Layer w0.254: QC1.3@13.97,31.672 15.547,31.672 R1.2@15.6,31.725
NetQC4_3: QC4.3 R2.1 | length 2.6
  Top Layer w0.254: QC4.3@37.443,31.337 38.745,31.337 38.745,31.024 38.75,31.019 38.75,30.175 R2.1@38.9,30.175
NetR11_1: R11.1 R16.2 U1.9 | length 3.7
  Top Layer w0.254: U1.9@8.5,51.1 9.3,51.1 9.75,51.55 R16.2@10.8,51.55 R11.1@10.8,50.35
NetR14_2: R14.2 U1.16 | length 4.2
  Top Layer w0.254: R14.2@1.15,50.85 1.15,51.35 1.45,51.65 3.55,51.65 4.1,51.1 U1.16@4.5,51.1
NetR15_2: R15.2 U1.13 | length 2.9
  Top Layer w0.254: U1.13@6,51.1 6,51.5 6.45,51.95 6.85,51.95 v6(6.9,51.9)
  Bottom Layer w0.254: v6(6.9,51.9) 7.1,52.1 R15.2@7.1,53.25
NetR17_2: R17.2 U1.14 | length 4.4
  Top Layer w0.254: U1.14@5.5,51.1 5.5,51.85 v6(5.55,51.9)
  Bottom Layer w0.254: v6(5.55,51.9) 5.519,51.9 5.509,51.909 5.6,52 5.6,52.2 5.6,53.5 6.55,54.45 R17.2@7.1,54.45
NetR20_1: R20.1 R21.2 U3.7 | length 2.8
  Top Layer w0.254: U3.7@4.65,32.7 5.3,32.7 v6(5.4,32.8)
  Bottom Layer w0.254: R21.2@5.15,30.9 5.15,32.55 v6(5.4,32.8)
NetRC11_1: RC11.1 UC1.34 | length 3.5
  Top Layer w0.254: RC11.1@13.802,26.821 13.802,25.897 14.125,25.574 UC1.34@14.125,23.5
NetRC12_1: RC12.1 UC1.32 | length 3.4
  Top Layer w0.254: UC1.32@15.131,23.5 UC1.32@15.125,23.5 15.125,25.833 15.375,26.083 RC12.1@15.375,26.806
NetRC13_1: RC13.1 UC1.27 | length 7.3
  Top Layer w0.254: UC1.27@17.625,23.5 17.648,23.523 17.648,24.214 17.67,24.237 17.67,24.92 17.693,24.943 17.693,24.947 18.541,25.795 18.541,26.552 19.544,27.555 20.305,27.555 20.673,27.555 21.036,27.192 21.036,26.814 RC13.1@21.35,26.5
NetRC14_2: RC14.2 UC1.10 | length 3
  Top Layer w0.254: v1(16.1,16.136) 16.118,16.118 16.625,16.625 UC1.10@16.625,17.7
  Bottom Layer w0.254: v1(16.1,16.136) 16.1,16.736 RC14.2@16.525,17.16
NetRC15_1: RC15.1 UC1.29 | length 7.8
  Top Layer w0.254: UC1.29@16.625,23.5 16.67,23.545 16.67,24.63 18.05,26.01 18.05,26.671 19.659,28.281 RC15.1@21.409,28.281
NetRC17_2: RC17.2 UC1.13 | length 5.7
  Top Layer w0.254: RC17.2@16.65,13.05 16.65,13.4 17.105,13.855 17.894,13.855 18.125,14.086 UC1.13@18.125,17.7
NetRC18_2: RC18.2 UC1.14 | length 4.9
  Top Layer w0.254: RC18.2@18.1,13.05 18.1,13.45 18.625,13.975 UC1.14@18.625,17.7
NetRC19_2: RC19.2 UC1.15 | length 5.8
  Top Layer w0.254: UC1.15@19.125,17.7 19.125,12.675 RC19.2@19.7,12.1
nFLT_DISCH: UC1.7
PSM_DISCH_EN: R6.2 RC7.2 UC1.12 | length 4.9
  Top Layer w0.254: v1(17.5,15.45) 17.625,15.575 UC1.12@17.625,17.7
  Bottom Layer w0.254: RC7.2@15.65,15.05 15.9,14.8 R6.2@17.5,14.8 v1(17.5,15.45)
SGND: C4.1 C5.1 C6.1 C7.1 C8.1 C9.1 C10.2 C11.2 C12.2 C13.2 C14.2 C15.1 C16.1 C19.2 C20.2 C21.2 C22.2 C23.2 CC1.2 CC2.2 CC3.2 CC4.2 CC5.2 CC6.2 CC7.2 CC8.2 CC9.2 CC10.2 CC11.2 CC12.2 CC13.2 CC14.2 CC15.2 CC16.2 CC17.2 CC18.2 CC19.2 CC20.2 CC21.2 CC22.2 CC23.2 CC26.2 CC27.2 CC28.2 CC29.2 CC30.2 CC31.2 CC32.2 CC33.2 CC34.2 CC35.1 CC37.2 CC38.2 CC39.2 CC40.2 CC41.1 CC44.1 CC45.2 CC46.2 DC3.1 DC3.2 DC3.3 DC3.4 DC4.1 DC4.2 DC4.3 DC4.4 J1.4 QC3.4 QC3.6 QC3.14 QC4.4 QC4.6 QC4.14 R3.1 R4.1 R7.1 R15.1 R16.1 R17.1 R21.1 R22.1 RC10.1 RC14.1 RC17.1 RC18.1 RC19.1 U1.17 U1.23 U1.24 U1.25 U1.26 U1.30 U2.2 U3.4 UC1.17 UC1.22 UC1.23 UC1.30 UC1.39 | length 114.7
  Top Layer w0.254: C8.1@1.7,45.684 1.7,45 v4(2.05,44.65) ; C12.2@2.5,50.85 3.25,50.85 3.6,50.5 U1.17@3.6,49.95 5.05,49.95 v3(5.15,50.05) ; v1(6.45,29.85) 6.35,29.95 R22.1@6.35,30.55 C23.2@7.6,30.55 ; CC39.2@10.55,24.35 11.263,24.35 11.546,24.067 v1(11.543,24.064) ; R16.1@12,51.55 13,51.55 v4(13.05,51.5) ; UC1.39@16.125,21.1 UC1.30@16.125,23.5 16.125,24.875 v1(16.6,25.35) ; v1@16.7,25.4 17.55,26.25 17.55,27.6 16.525,28.625 v1(16.525,28.988) 19.046,28.988 20.068,30.01 20.068,30.386 QC3.14@20.07,30.388 ; UC1.39@19.625,22.239 UC1.23@19.625,23.5 ; UC1.22@20.125,23.5 UC1.39@20.128,22.019 ; v2(20.255,33.488) 20.255,32.647 20.738,32.163 QC3.4@21.495,32.163 21.982,32.163 22.363,31.783 CC30.2@22.896,31.783 ; QC4.14@36.018,30.062 36.018,28.882 36.35,28.55 v1(36.9,28.55) ; QC4.4@37.443,31.837 37.887,31.837 v1(38.4,32.35) 38.8,32.75 CC31.2@39.35,32.75
  Top Layer w0.5: C22.2@1.5,27 2.1,27 ; U2.2@2.1,25.775 2.1,27 ; v4(3.9,30.55) 4.026,30.676 U3.4@4.026,30.919 ; U3.4@4,30.55 4,27.5 v1@3.5,27 ; C13.2@4.5,24.95 4.5,26 v1@3.5,27 ; 2.1,27 C14.2@2.7,27 v1@3.5,27
  Top Layer w0.508: v1(5.775,16.946) v1@5.822,16.899
  Signal Layer 4 w0.254: v1(36.9,28.55) 36.9,30.85 v1(38.4,32.35)
  Signal Layer 4 w0.508: 5.578,21.17 6.225,20.524 v1@6.225,18.25 ; 10.65,18.901 10.65,23.305 11.409,24.064 v1(11.543,24.064) v1@11.549,24.064
  Signal Layer 1 w0.254: v4(2.05,44.65) 2.05,46.95 v3(5.15,50.05)
  Signal Layer 1 w1: v5(11.2,38.65) 19.3,46.75 19.3,59.65 20.2,60.55 36.5,60.55 J1.4@37.2,61.25
  Bottom Layer w0.254: R21.1@6.35,30.9 6.45,30.8 v1(6.45,29.85) ; v3(7.775,50.05) 7.91,50.185 8.335,50.185 8.5,50.35 8.5,53.05 R15.1@8.3,53.25 R17.1@8.3,54.45 ; 16.6,24.268 16.625,24.243
  Bottom Layer w0.6: CC32.2@15.1,23.834 16.166,23.834 16.6,24.268 v1(16.6,25.35)
  other v1: 37.818,4.098 38.71,4.102 37.818,4.998 38.71,5.002 37.818,5.848 38.71,5.852 37.808,6.646 38.7,6.65 37.808,7.546 38.7,7.55 37.808,8.396 38.7,8.4 37.85,9.248 38.742,9.252 37.85,10.098 38.742,10.102 17.9,10.5 37.85,10.998 38.742,11.002 37.85,11.848 38.742,11.852 6.3,11.952 9.6,12.05 17.4,12.05 37.854,12.69 38.746,12.694 37.854,13.59 38.746,13.594 37.854,14.44 38.746,14.444 20.2,16.45 6.475,18.25 8.95,20.974 3.545,27.014 2.395,35.214 2.395,35.914 2.395,36.564
  other v2: 23.985,24.489 23.985,25.042 23.878,26.5 23.9,27.1 23.9,29.05 23.9,29.55 24.05,31.205 24.011,31.772 36.203,33.162 37.343,33.162 22.595,33.378 23.145,33.378 23.695,33.378 21.395,33.488 22.602,33.932 23.152,33.932 23.702,33.932 22.591,34.945 23.141,34.945 23.691,34.945 22.598,35.499 23.148,35.499 23.698,35.499 36.203,35.762 37.343,35.762 20.255,36.088 21.395,36.088 22.602,36.353 23.152,36.353 23.702,36.353 22.609,36.906 23.159,36.906 23.709,36.906
  other v3: 12.425,19.4 13.625,19.4 14.825,19.4 16.025,19.4 17.225,19.4 18.425,19.4 19.625,19.4 20.825,19.4 12.425,20.6 13.625,20.6 14.825,20.6 16.025,20.6 17.225,20.6 18.425,20.6 19.625,20.6 20.825,20.6 12.425,21.8 13.625,21.8 14.825,21.8 16.025,21.8 17.225,21.8 18.425,21.8 19.625,21.8 20.825,21.8 5.15,48.966 6.463,48.966 7.775,48.966 6.463,50.05
  other v4: 3.9,31.3 5.324,44.602 5.95,44.6 4.694,44.62 25.439,60.413 26.289,60.413 27.139,60.413 27.989,60.413 28.889,60.413
  other v5: 2.05,64.75 2.05,66.3 2,67.95
SW2: C1.1 CC25.2 CC43.2 DC2.1 DC2.2 DC2.3 DC2.4 DC4.5 DC6.2 LC1.2 QC2.4 QC2.6 QC2.14 QC4.7 QC4.8 UC1.25 | length 27
  Top Layer w0.254: UC1.25@18.625,23.5 18.67,23.545 18.67,24.418 v1(19.1,24.848) 19.602,25.35 CC43.2@20.2,25.35 ; QC2.14@30.35,30 30.35,29.779 30.42,29.709 30.42,29.53 30.815,29.135 v1(30.815,28.471) ; QC2.4@31.775,31.775 CC25.2@32.525,31.775 ; CC25.2@32.776,31.904 32.843,31.837 QC4.8@33.743,31.837 ; 33.078,32.828 33.1,32.85
  Top Layer w0.508: CC25.2@32.776,31.904 32.776,32.724
  Signal Layer 3 w0.254: v1(19.1,24.848) 19.902,25.65 21.5,25.65 24.4,28.55 v1@30.65,28.55
  Bottom Layer w0.254: v1(19.1,24.848) 19.787,24.162 DC6.2@19.787,23.704 ; v1(30.815,28.471) 30.815,28.539 30.938,28.662 30.938,29.288 31.4,29.75 31.4,32.801 31.549,32.95 32.05,32.95
  other v2: 30.535,33.1 31.675,33.1 33.843,33.162 34.983,33.162 30.535,35.7 31.675,35.7 33.843,35.762 34.983,35.762
UC_COMP_DIR_AUX: R8.1 | length 14.1
  Top Layer w0.254: 18.95,3.4 19.1,3.55 19.1,5.35 24.068,10.318 24.068,14.379 24.2,14.511 R8.1@24.2,15.3
UC_En_Disable_AUX: R10.1 | length 15.2
  Top Layer w0.254: R10.1@5.45,12.3 5.45,9.85 7.2,8.1 12.15,8.1 14.2,6.05 14.2,4.5 14.2,3.6
UC_FAN_CLK: J1.1 | length 102.4
  Top Layer w0.254: v1(5.95,6) 7.1,4.85 7.1,3.8
  Signal Layer 3 w0.254: v1(5.95,6) 3.2,6 0.6,8.6 0.6,61.4 8.2,69 35.45,69 J1.1@37.2,67.25
UC_FAN_PWM: R18.1 | length 104.3
  Top Layer w0.254: 9.4,3.65 9.45,3.7 v4(9.45,6)
  Signal Layer 3 w0.254: v4(9.45,6) 9.45,10.75 4.65,15.55 4.65,29.955 6.15,31.455 6.15,33.65 1.032,38.768 1.032,61.221 8.161,68.35 31.7,68.35 33.45,66.6 v4(33.45,62.1)
  Bottom Layer w0.254: v4(33.45,62.1) 33.5,62.15 R18.1@33.5,63.45
UC_MODE_AUX: R6.1 | length 11.8
  Top Layer w0.254: 16.55,2.4 v7(16.55,6.9)
  Bottom Layer w0.254: v7(16.55,6.9) 16.5,6.95 16.5,12.8 R6.1@17.5,13.8
UC_VFB_DIR_AUX: R9.1 | length 13.4
  Top Layer w0.254: 21.4,3.6 21.4,6.95 24.5,10.05 24.5,14.2 R9.1@25.6,15.3
VAUX: C4.2 C5.2 C6.2 C7.2 CC11.1 CC12.1 CC13.1 CC14.1 CC15.1 CC16.1 CC17.1 CC18.1 CC19.1 CC20.1 CC21.1 CC22.1 CC23.1 CC26.1 CC27.1 CC28.1 CC29.1 CC34.1 DC2.5 QC2.7 QC2.8 R5.2 R11.2 U1.1 U1.2 U1.3 U1.27 U1.28 U1.29 UC1.20 | length 8.3
  Top Layer w0.254: U1.3@9.4,46.95 9.4,46.616 U1.2@9.566,46.45 ; v4(11.85,49.05) 12,49.2 R11.2@12,50.35 ; UC1.20@21.125,23.5 21.625,24 CC34.1@23.055,24 ; R5.2@24.05,6.05 25.902,4.198 v1(27.468,4.198)
  other v1: 28.36,4.202 27.468,5.098 28.36,5.102 27.468,5.948 28.36,5.952 27.458,6.746 28.35,6.75 27.458,7.646 28.35,7.65 27.458,8.496 28.35,8.5 27.5,9.348 28.392,9.352 27.5,10.198 28.392,10.202 27.5,11.098 28.392,11.102 27.5,11.948 28.392,11.952 27.504,12.79 28.396,12.794 27.504,13.69 28.396,13.694 27.504,14.54 28.396,14.544 27.5,15.448 28.392,15.452 27.5,16.348 28.392,16.352 27.5,17.198 28.392,17.202 27.504,18.04 28.396,18.044 27.504,18.94 28.396,18.944 27.504,19.79 28.396,19.794 27.5,20.548 28.392,20.552 27.5,21.448 28.392,21.452 27.5,22.298 28.392,22.302 27.504,23.14 28.396,23.144 27.504,24.04 28.396,24.044 27.504,24.89 28.396,24.894
  other v2: 28.15,33.1 29.315,33.1 28.175,35.7 29.315,35.7
  other v3: 7.375,45.65 8.6,45.65 7.375,46.558 8.6,46.558 7.375,47.466 8.334,47.466
VAUX_FB: CC33.1 R5.1 R7.2 R9.2 UC1.19 | length 15.5
  Top Layer w0.254: UC1.19@21.125,17.7 21.275,17.55 CC33.1@22.855,17.55 R7.2@24.35,17.55 25,17.55 25.6,16.95 25.6,16.5 25.85,16.5 26.3,16.05 26.3,14.55 24.932,13.182 24.932,9.871 24.05,8.989 R5.1@24.05,7.65
VBATAUX: CC1.1 CC2.1 CC3.1 CC4.1 CC5.1 CC6.1 CC7.1 CC8.1 CC9.1 CC10.1 QC1.7 QC1.8 RC4.1 | length 3.1
  Top Layer w0.254: QC1.8@10.27,32.172 10.27,32.37 10.82,32.92 QC1.7@10.82,35.022
  other v2: 10.617,33.754 11.417,33.804 11.45,35.95 10.667,35.954
  other v5: 10.35,55.35 10.35,56.9 10.3,58.55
